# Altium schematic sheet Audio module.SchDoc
size A4
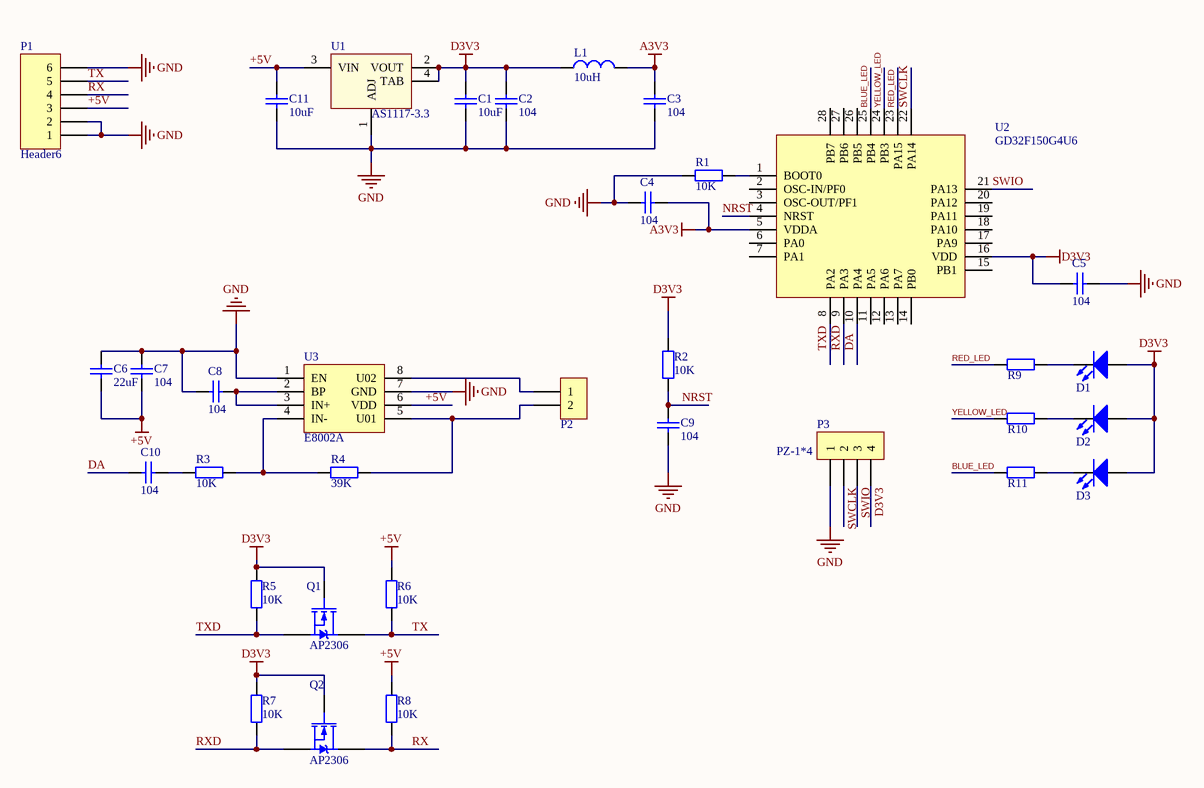
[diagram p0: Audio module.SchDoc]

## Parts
C1  value 10uF  [0603-2]  (hidden comment: Cap)
C2  value 104  [0603-2]  (hidden comment: Cap)
C3  value 104  [0603-2]  (hidden comment: Cap)
C4  value 104  [0603-2]  (hidden comment: Cap)
C5  value 104  [0603-2]  (hidden comment: Cap)
C6  value 22uF  [0603-2]  (hidden comment: Cap)
C7  value 104  [0603-2]  (hidden comment: Cap)
C8  value 104  [0603-2]  (hidden comment: Cap)
C9  value 104  [0603-2]  (hidden comment: Cap)
C10  value 104  [0603-2]  (hidden comment: Cap)
C11  value 10uF  [0603-2]  (hidden comment: Cap)
D1  RED_LED  [RES_0603]  (value not drawn)
D2  YELLOW_LED  [RES_0603]  (value not drawn)
D3  BLUE_LED  [RES_0603]  (value not drawn)
L1  value 10uH  [0805-1]  (hidden comment: Inductor)
P1  Header6  [HDR6X1_A]
P2  PZ-1*2  [HDR2X1_A]  (value not drawn)
P3  PZ-1*4  [HDR4X1_A]
Q1  AP2306  [SOT-23]
Q2  AP2306  [SOT-23]
R1  10K  [RES-0603]
R2  10K  [RES-0603]
R3  value 10K  [0603-1]  (hidden comment: Res1)
R4  value 39K  [0603-1]  (hidden comment: Res1)
R5  10K  [RES-0603]
R6  10K  [RES-0603]
R7  10K  [RES-0603]
R8  10K  [RES-0603]
R9  RES  [RES_0603]  (value not drawn)
R10  RES  [RES_0603]  (value not drawn)
R11  RES  [RES_0603]  (value not drawn)
U1  AS1117-3.3  [SOT-223]
U2  GD32F150G4U6  [QFN28-1]
U3  E8002A  [SOP-8]

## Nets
+5V: C6.2 C7.1 C11.2 P1.3 R6.2 R8.2 U1.3(VIN) U3.6(VDD)
A3V3: C3.2 C4.1 L1.2 U2.5(VDDA)
D3V3: C1.2 C2.2 C5.2 D1.1(A) D2.1(A) D3.1(A) L1.1 P3.4 R2.2 R5.2 R7.2 U1.2(VOUT) U1.4(TAB) U2.16(VDD)
GND: C1.1 C2.1 C3.1 C4.2 C5.1 C6.1 C7.2 C8.2 C9.1 C11.1 P1.1 P1.2 P1.6 P3.1 R1.2 U1.1(ADJ) U3.1(EN) U3.7(GND)
BLUE_LED: R11.1 U2.25(PB4)
DA: C10.2 U2.10(PA4)
NRST: C9.2 R2.1 U2.4(NRST)
RED_LED: R9.1 U2.23(PA15)
RX: P1.4 Q2.3(D) R8.1
RXD: Q2.2(S) R7.1 U2.9(PA3)
SWCLK: P3.2 U2.22(PA14)
SWIO: P3.3 U2.21(PA13)
TX: P1.5 Q1.3(D) R6.1
TXD: Q1.2(S) R5.1 U2.8(PA2)
YELLOW_LED: R10.1 U2.24(PB3)
NetC8_1: C8.1 U3.2(BP) U3.3(IN+)
NetC10_1: C10.1 R3.1
NetD1_2: D1.2(K) R9.2
NetD2_2: D2.2(K) R10.2
NetD3_2: D3.2(K) R11.2
NetP2_1: P2.1 U3.8(U02)
NetP2_2: P2.2 R4.2 U3.5(U01)
NetR1_1: R1.1 U2.1(BOOT0)
NetR3_2: R3.2 R4.1 U3.4(IN-)

Not connected (* = marked no-connect by the designer): Q1 G(1); Q2 G(1); U2 2(OSC-IN/PF0) 3(OSC-OUT/PF1) 6(PA0) 7(PA1) 11(PA5) 12(PA6) 13(PA7) 14(PB0) 15(PB1) 17(PA9) 18(PA10) 19(PA11) 20(PA12) 26(PB5) 27(PB6) 28(PB7)

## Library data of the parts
C1-C11 = Cap: 无极性电容
D1-D3 = LED
L1 = Inductor: 电感; Code_IEC: 1005
Q1 Q2 = MOSFET-N1: N-MOSFET1; PackageDocument: 1995/1996
R1-R8 = Res1: 贴片电阻
R9-R11 = RES: value: 1K
U1 = AS1117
